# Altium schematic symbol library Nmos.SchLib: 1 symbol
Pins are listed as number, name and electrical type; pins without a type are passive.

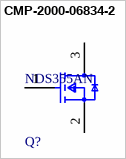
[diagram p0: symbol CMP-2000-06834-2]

## CMP-2000-06834-2
designator Q?, comment NDS355AN
MOSFET N-CH 30V 1.7A SSOT3; Manufacturer: ON Semiconductor; Gate To Source Voltage: 20V; Threshold Vgs Min: 1V; Pulse Drain Current: 10A; Number Of N Channels: 1; Typ Forward Diode Voltage: 0.8V; Input Capacitace At Vds: 195pF @ 15V; Turn Off Delay Time: 13ns; Gate Charge At Vgs: 3.5nC @ 5V; Rthja Max: 250°C/W; Standoff Height: 0.013mm; Max Forward Diode Voltage: 1.2V; Power Dissipation: 0.46W; Depletion Mode: False; Threshold Vgs Max: 2V; Drain To Source Resistance: 0.105Ω; Turn On Delay Time: 10ns; Max Junction Temp: +150°C; Transconductance: 3.5S
footprint FP-527AG-01-IPC_A
footprint FP-527AG-01-IPC_C
footprint FP-527AG-01-IPC_B
pins: 1 G, 2 S, 3 D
